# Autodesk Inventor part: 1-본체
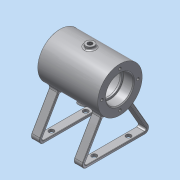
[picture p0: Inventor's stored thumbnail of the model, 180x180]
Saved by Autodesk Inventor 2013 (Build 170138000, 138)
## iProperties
Created: 2016-03
Part Number: 1-본체
Material: 알루미늄 6061
Document SubType Name: Modeling
Designer: Administrator
Mass: 213.448 g
Surface Area: 334.281 cm^2
Volume: 78.7632 cm^3
Density: 2.71 g/cm^3
Author: Administrator
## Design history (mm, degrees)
sketch "스케치1"
  geometry: C1 r 26 at (0, 0); 1 further point
  constraints: 1 centre point, 1 coincident
  dimensions: "d0" = 52 diameter of C1
extrude "돌출1" new body sketch "스케치1" stored distance "d2" = 70; taper "d3" = 0 deg
node "작업 평면1"
sketch "스케치2"
  geometry: C1 r 5 at (0, 0); 1 further point
  constraints: 1 centre point, 1 coincident
  dimensions: "d5" = 10 diameter of C1
extrude "돌출2" join sketch "스케치2" distance "d7" = 26; taper "d8" = 0 deg
sketch "스케치3"
  geometry: L1 (0, 0)-(0, -26); L2 (0, 0)-(7.506, -28.012); L3 (-1.968, -15.836)-(1.71, -29.565); L4 (1.71, -29.565)-(7.506, -28.012); L5 (7.506, -28.012)-(3.827, -14.283); L6 (3.827, -14.283)-(-1.968, -15.836); 1 further point
  constraints: 12 end point, 3 parallel, 1 collinear, 1 perpendicular, 1 vertical, 1 vertical alignment, 1 other
  dimensions: "d9" = 15 deg angle of L2 L1; "d10" = 12 diameter of L3 L2; "d12" = 29 distance from line of L4 point (0, 0)
revolve "회전1" sketch "스케치3" stored, may be unused: angle "d13" = 90 deg
node "작업 평면2"
sketch "스케치4"
  geometry: L1 (-16.613, -20)-(-38.264, -57.5); L2 (-33.934, -65)-(33.934, -65); L3 (38.264, -57.5)-(16.613, -20); L4 (0, 0)-(0, -65); L5 (-16.613, -20)-(16.613, -20); A1 r 5 centre (-33.934, -60) between (-38.264, -57.5) and (-33.934, -65); A2 r 5 centre (33.934, -60) between (33.934, -65) and (38.264, -57.5); A3 r 26 centre (0, 0) between (-16.613, -20) and (16.613, -20) reference
  constraints: 10 end point, 7 point on circle, 3 tangent, 2 centre point, 1 equal length, 1 equal radius, 1 horizontal, 1 midpoint, 1 perpendicular, 1 vertical alignment
  dimensions: "d16" = 5 radius of A1; "d20" = 45 distance between parallel lines of L2 L5; "d21" = 65 distance from line of L4.start L2; "d23" = 30 deg angle of L4 L1; "d24" = 30 deg angle of L3 L4
extrude "돌출3" new body sketch "스케치4" distance "d25" = 10; taper "d26" = 0 deg
sketch "스케치5"
  geometry: L1 (-16.613, -20)-(-38.264, -57.5) reference; L2 (38.264, -57.5)-(16.613, -20) reference; L3 (-33.934, -65)-(33.934, -65) reference; L4 (-14.183, -21.791)-(-35.666, -59); L5 (-33.934, -62)-(33.934, -62); L6 (35.666, -59)-(14.183, -21.791); A1 r 5 centre (-33.934, -60) between (-38.264, -57.5) and (-33.934, -65) reference; A2 r 26 centre (0, 0) between (-16.613, -20) and (16.613, -20) reference; A3 r 5 centre (33.934, -60) between (33.934, -65) and (38.264, -57.5) reference; A4 r 2 centre (-33.934, -60) between (-35.666, -59) and (-33.934, -62); A5 r 2 centre (33.934, -60) between (33.934, -62) and (35.666, -59); A6 r 26 centre (0, 0) between (-14.183, -21.791) and (14.183, -21.791); 1 further point
  constraints: 8 end point, 8 point on circle, 3 centre point, 1 coincident, 1 concentric, 2 other
  dimensions: "d27" = 3 distance between parallel lines of L1 L4; "d28" = 3 distance between parallel lines of L2 L6; "d29" = 3 distance between parallel lines of L3 L5
  node "투영된 루프2"
feature "결합1"
  node "솔리드2"
extrude "돌출4" cut sketch "스케치5" distance "d30" = 10; taper "d31" = 0 deg
node "작업 평면4"
sketch "스케치7"
  geometry: L1 (-6.533, -4.268)-(-6.533, 4.268); L2 (-6.533, 4.268)-(6.533, 4.268); L3 (6.533, 4.268)-(6.533, -4.268); L4 (6.533, -4.268)-(-6.533, -4.268); L5 (-26, -35)-(26, -35) reference; L6 (-26, -35)-(-26, 35) reference; 4 further points
  constraints: 2 midpoint, 1 horizontal alignment, 1 vertical alignment, 2 other
  dimensions: "d38" = 26 distance from line of L6 point (0, 0); "d39" = 35 distance from line of point (0, 0) L5; "d40" = 13.0662 distance between parallel lines of L1 L3; "d41" = 8.53659 distance between parallel lines of L2 L4; "d42" = 6.5331 distance from line of point (0, 0) L3
feature "엠보싱2" sketch "스케치7" dims "d16" = 5, "d20" = 45, "d21" = 65, "d23" = 30 deg, "d24" = 30 deg, "d43" = 0.5, "d44" = 0
hole "구멍1" diameter "d47" = 28; stored, may be unused: countersink angle "d51" = 90 deg, drill point angle "d53" = 0 deg; dims "d45" = 10, "d46" = 10, "d48" = 6, "d49" = 32, "d50" = 12, "d52" = 8
hole "구멍2" diameter "d56" = 32; stored, may be unused: countersink angle "d60" = 90 deg, drill point angle "d62" = 0 deg; dims "d54" = 10, "d55" = 10, "d57" = 6, "d58" = 32, "d59" = 12, "d61" = 12
sketch "스케치8"
  geometry: L1 (-16, 35)-(16, 35) reference; L2 (16, -35)-(-16, -35) reference; L3 (0, 35)-(0, -35); L4 (18, 21)-(0, 21); L5 (0, 21)-(0, -21); L6 (0, -21)-(18, -21); L7 (21, -18)-(21, 18); A1 r 3 centre (18, 18) between (21, 18) and (18, 21); A2 r 3 centre (18, -18) between (18, -21) and (21, -18); 4 further points
  constraints: 10 end point, 4 midpoint, 4 point on circle, 4 tangent, 2 centre point, 2 coincident, 2 parallel, 1 equal radius, 1 horizontal, 1 perpendicular, 1 vertical alignment
  dimensions: "d68" = 42 diameter of L7 L3; "d70" = 42 distance between parallel lines of L4 L6; "d71" = 3 radius of A1
revolve "회전2" sketch "스케치8" stored, may be unused: angle "d72" = 90 deg
sketch "스케치9"
  geometry: 2 further points
  constraints: 1 vertical alignment
  dimensions: "d73" = 21 distance of point (0, 0) point (0, 21)
hole "구멍3" sketch "스케치9" at (0, 21) diameter "d74" = 3.242; stored, may be unused: countersink angle "d78" = 90 deg, drill point angle "d80" = 118 deg; dims "d75" = 8, "d76" = 32, "d77" = 12, "d79" = 10
sketch "스케치10"
  geometry: L1 (-5, 0)-(-5, -10) reference; L2 (-5, -50)-(-5, -60) reference; 7 further points
  constraints: 4 horizontal alignment, 2 midpoint, 2 vertical alignment
  dimensions: "d84" = 20 horizontal distance of point (33.934, -30) point (13.934, -5); "d85" = 40 distance of point (53.934, -5) point (13.934, -5)
hole "구멍4" sketch "스케치10" at (13.934, -5), (53.934, -5), (13.934, -55), (53.934, -55) diameter "d86" = 6; stored, may be unused: countersink angle "d90" = 90 deg, drill point angle "d92" = 118 deg; dims "d87" = 6, "d88" = 32, "d89" = 12, "d91" = 10
hole "구멍5" diameter "d95" = 5.188; stored, may be unused: countersink angle "d99" = 90 deg, drill point angle "d101" = 0 deg; dims "d96" = 19, "d97" = 32, "d98" = 12, "d100" = 20, "d104" = 10, "d105" = 10
hole "구멍6" diameter "d106" = 5.188; stored, may be unused: countersink angle "d110" = 90 deg, drill point angle "d112" = 0 deg; dims "d102" = 10, "d103" = 10, "d107" = 14, "d108" = 32, "d109" = 12, "d111" = 15
fillet "모깎기1" dims "d113" = 2
chamfer "모따기1" distance "d114" = 1; stored, may be unused: second distance "d115" = 2, angle "d116" = 45 deg
fillet "모깎기2" dims "d117" = 0.3
fillet "모깎기3" dims "d118" = 0.5
fillet "모깎기4" dims "d119" = 0.5
fillet "모깎기5" dims "d120" = 3
node "솔리드1"
mirror "대칭1"
mirror "대칭2"
pattern_circular "원형 패턴1" dims angle "d82" = 360 deg
mirror "대칭3"
node "투영된 루프1"
other parameters: "d4" = 29
